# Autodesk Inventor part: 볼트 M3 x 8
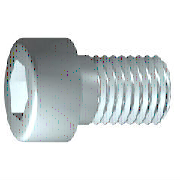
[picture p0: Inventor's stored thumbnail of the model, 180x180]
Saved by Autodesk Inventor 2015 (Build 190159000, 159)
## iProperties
IsCustomPart: 0
Created: 2012-02
Part Number: 볼트 M3 x 8
Material: 스테인리스강
Description: 6각 소켓 머리 캡 나사
Document SubType Name: Modeling
Standard: ISO 4762
Designer: mduedu
Standard Revision: Fourth edition 2004-03-01
Standards Organization: ISO
Language: ko-KR
Size Designation: M3 x 8
Categories: <MemberInstance><Categories><Category DisplayName="조임쇠" InternalName="e4da775c-781d-43d5-af7c-5136215cf5a6" Mnemonic="FSTN"><Category DisplayName="볼트" InternalN
Density: 8.08 g/cm^3
Mass: 0.955869 g
Surface Area: 1.83001 cm^2
Volume: 0.118301 cm^3
Appearance: 반광택
Author: mduedu
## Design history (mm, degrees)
sketch "스케치1"
  geometry: L1 (-0.867, 0)-(8, 0); L2 (8, 0)-(8, 1.5); L3 (8, 1.5)-(1.25, 1.5); L4 (1.25, 1.5)-(0.943, 1.5); L5 (0.943, 1.5)-(0, 1.5); L6 (0, 1.5)-(0, 2.75); L7 (0, 2.75)-(-3, 2.75); L8 (-3, 2.75)-(-3, 1.443); L9 (-3, 1.443)-(-1.7, 1.443); L10 (-1.7, 1.443)-(-0.867, 0); L11 (-5.2, 0)-(10.2, 0) reference; L12 (0, -0.55)-(0, 3.3) reference; L13 (1.25, 1.5)-(0, 1.5)
  constraints: 22 end point, 6 parallel, 2 collinear, 2 perpendicular, 1 horizontal, 1 point on line
  dimensions: "d1" = 6.75 distance from line of L3.end L2 (= GEL); "d2" = 0.30683 distance of L4.end L3.end (computed from GAL); "d3" = 3 distance between parallel lines of L8 L6 (= KOH); "d4" = 1.3 distance of L8.end L9.end (= INTI); "d5" = 60 deg angle of L10 L1; "d6" = 3 diameter of L3 L1 (= GD); "d7" = 3 diameter of L5 L1 (= BDM); "d8" = 2.88675 diameter of L9 L1 (= 1.1547 x SW); "d9" = 5.5 diameter of L7 L1 (= KOD); "d26" = 8 distance between parallel lines of L12 L2 (= NLG)
revolve "본체" sketch "스케치1" stored, may be unused: angle "d10" = 90 deg
sketch "스케치2"
  geometry: L1 (0, -3.85)-(0, 3.85) reference; L2 (-3.85, 0)-(3.85, 0) reference; L3 (1.443, 0)-(0.722, -1.25); L4 (0.722, -1.25)-(-0.722, -1.25); L5 (-0.722, -1.25)-(-1.443, 0); L6 (-1.443, 0)-(-0.722, 1.25); L7 (-0.722, 1.25)-(0.722, 1.25); L8 (0.722, 1.25)-(1.443, 0); 2 further points
  constraints: 12 end point, 1 coincident, 1 horizontal alignment, 1 point on line, 12 other
extrude "슬롯" join sketch "스케치2" stored distance "d11" = 10; taper "d12" = 0 deg
workplane "Work Plane1"
fillet "Fillet2" dims "d30" = 0.1 (= R)
body "Solid1"
fillet "모깎기1" dims "d17" = 0.3 (= RR)
feature "스레드" dims "d13" = 6.75 (= GEL), "d14" = 0
chamfer "모따기1" distance "d15" = 0.30673 (= -0.5 x SPD + 0.5 x GD); stored, may be unused: second distance "d16" = 0.30673 (= GUL), angle "d27" = 45 deg
other parameters: "GD" = 3 [user parameter; used in 2 equation terms], "NLG" = 8 [user parameter; used in 1 equation term], "GEL" = 6.75 [user parameter; used in 2 equation terms], "KOD" = 5.5 [user parameter; used in 1 equation term], "KOH" = 3 [user parameter; used in 1 equation term], "INTI" = 1.3 [user parameter; used in 1 equation term], "GAL" = 0.30673 (= 0.61345 x PTC) [user parameter; used in 1 equation term], "GUL" = 0.30673 (= 0.61345 x PTC) [user parameter; used in 1 equation term], "BDM" = 3 (= NND) [user parameter; used in 1 equation term], "SW" = 2.5 [user parameter; used in 2 equation terms], "RR" = 0.3 [user parameter; used in 1 equation term], "SPD" = 2.38655 (= NND - 1.2269 x PTC) [user parameter; used in 1 equation term], "d19" = 0, "d28" = 0, "d29" = 0, "R" = 0.1 [user parameter; used in 1 equation term], "TOA" = 30 deg [user parameter], "GD1" = 2.38655 (= THREADDIA - 1.2269 x PTC) [user parameter], "THREADDIA" = 3 [user parameter; used in 1 equation term], "FAWI" = 45 deg [user parameter], "PTC" = 0.5 [user parameter; used in 5 equation terms], "NND" = 3 [user parameter; used in 2 equation terms], "E0" = 2.8875 (= 1.155 x SW) [user parameter]
